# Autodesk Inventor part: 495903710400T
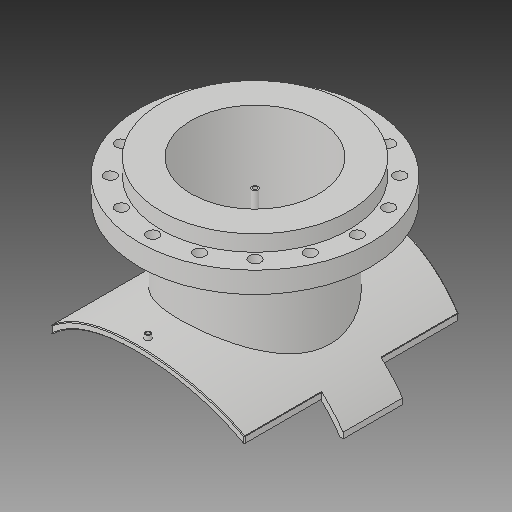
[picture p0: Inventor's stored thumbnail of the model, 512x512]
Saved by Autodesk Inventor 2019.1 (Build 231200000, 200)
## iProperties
Created: 2017-10
Part Number: 495903710400T
Material: Generic
Description: PLASSON FLANGED BRANCH SADDLE 710X400_
Document SubType Name: Modeling
Designer: KIM
Mass: 2339.99 g
Surface Area: 3251.55 cm^2
Volume: 2339.99 cm^3
Density: 1 g/cm^3
Appearance: Default
Author: KIM
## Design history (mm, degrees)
derived "495904_495903.ipt"
feature "Solid1::495904_495903.ipt"
feature "Solid2::495904_495903.ipt"
tag "TaggingFeature1"
body "Solid1"
other parameters: "d1" = 15, "d2" = 495, "d4" = 0, "d6" = 152.5, "d7" = 0, "d12" = 380.6, "d13" = 14, "d14" = 274.5, "d16" = 5 deg, "d18" = 4, "d19" = 14, "d20" = 0, "d21" = 3, "d22" = 0, "d36" = 274.5, "d38" = 0, "d39" = 2, "d41" = 327, "d42" = 482, "d43" = 595, "d44" = 224, "d46" = 385.6, "d47" = 16, "d48" = 10.4, "d49" = 196, "d51" = 724.2, "d53" = 0, "d55" = 262.5, "d57" = 0, "d59" = 360 deg, "d61" = 54, "d63" = 0, "d67" = 15, "d70" = 0, "d71" = 2, "d_1" = 482, "x_" = 15, "D_" = 16, "DN_" = 327, "D_1" = 595, "t_" = 54, "Dp_" = 525
